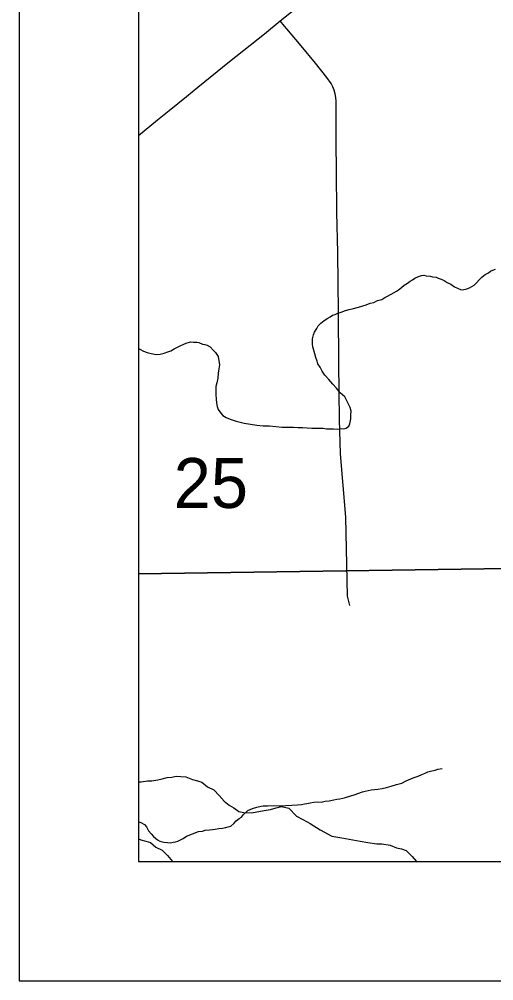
# Model space of a CAD drawing. Extents: x -21.1 to 50.3, y -4.9 to 22.1.
# Drawn here: x 2 to 2.398, y 14 to 14.806 of the extents above; entities that cross this region are included whole.
import ezdxf

# ---------------------------------------------------------------- set-up
doc = ezdxf.new("R2010")
doc.units = 0
for name, color, linetype in [('GM_X_Corporation', 7, 'Continuous'), ('GM_X_County', 7, 'Continuous'), ('GM_X_Minor_River', 7, 'Continuous'), ('GM_X_Rail_Line_Text', 7, 'Continuous'), ('GM_X_Section_Text', 7, 'Continuous'), ('GM_X_State_Route', 7, 'Continuous'), ('GM_X_Township_Road', 7, 'Continuous'), ('SH_Cut_Line', 7, 'Continuous'), ('SH_Data', 7, 'Continuous')]:
    doc.layers.add(name, color=color, linetype=linetype)

msp = doc.modelspace()

# ---------------------------------------------------------------- linework, layer by layer
at = {"layer": 'GM_X_Corporation'}
for points in [[(2.1, 15.34422), (2.1, 14.34116), (2.8725, 14.35222), (2.86184, 15.35457)], [(2.1, 14.34116), (2.1, 14.1), (2.87676, 14.1), (2.8725, 14.35222)]]:
    msp.add_lwpolyline(points, close=True, dxfattribs=at)
at = {"layer": 'GM_X_County'}
msp.add_lwpolyline([(8.9, 14.74638), (8.9, 20.9), (2.1, 20.9), (2.1, 14.1), (8.89319, 14.1)], dxfattribs=at)
at = {"layer": 'GM_X_Minor_River'}
for points in [[(2.26969, 14.56043), (2.27352, 14.56188), (2.27658, 14.56258), (2.28002, 14.56365), (2.28307, 14.56436), (2.28613, 14.56506), (2.28804, 14.56578), (2.29071, 14.56649), (2.29416, 14.56795), (2.29722, 14.56865), (2.30029, 14.57011), (2.30373, 14.57119), (2.30642, 14.57265), (2.30872, 14.57375), (2.3141, 14.57707), (2.31602, 14.57817), (2.31795, 14.57928), (2.32026, 14.58113), (2.32258, 14.58299), (2.32527, 14.58483), (2.32758, 14.58631), (2.3295, 14.58741), (2.33143, 14.5889), (2.3345, 14.59036), (2.33718, 14.59107), (2.33908, 14.59141), (2.34098, 14.591), (2.34439, 14.59056), (2.34628, 14.59014), (2.34932, 14.5897), (2.3512, 14.58891), (2.35347, 14.58811), (2.35611, 14.58692), (2.35874, 14.58535), (2.36175, 14.58378), (2.36476, 14.58182), (2.3674, 14.58063), (2.36965, 14.57945), (2.37155, 14.57904), (2.37499, 14.58011), (2.37728, 14.58083), (2.3792, 14.58193), (2.38113, 14.58304), (2.38306, 14.5849), (2.38539, 14.58751), (2.38771, 14.58975), (2.39042, 14.59198), (2.39311, 14.59344), (2.39504, 14.59493), (2.39695, 14.59565), (2.39924, 14.59637)], [(2.1, 14.52995), (2.10107, 14.52939), (2.10408, 14.52782), (2.1071, 14.52662), (2.11051, 14.5258), (2.11467, 14.52496), (2.1181, 14.52528), (2.12154, 14.52597), (2.1246, 14.52706), (2.1269, 14.52815), (2.12997, 14.52961), (2.13266, 14.53108), (2.13535, 14.53255), (2.13803, 14.53364), (2.13994, 14.53436), (2.14338, 14.53544), (2.14605, 14.53539), (2.1487, 14.53534), (2.1506, 14.53493), (2.15362, 14.53373), (2.15551, 14.53331), (2.15741, 14.5329), (2.16004, 14.53133), (2.16265, 14.52862), (2.16451, 14.52669), (2.16673, 14.52323), (2.16774, 14.51638), (2.1673, 14.51297), (2.16684, 14.50918), (2.16639, 14.50501), (2.16556, 14.50123), (2.16474, 14.49821), (2.16468, 14.49479), (2.16461, 14.49137), (2.16492, 14.48757), (2.16524, 14.48453), (2.16595, 14.48147), (2.16666, 14.4788), (2.16888, 14.47572), (2.17075, 14.47379), (2.17338, 14.47222), (2.17677, 14.47064), (2.18168, 14.46903), (2.18849, 14.46738), (2.1938, 14.46653), (2.19911, 14.46567), (2.20442, 14.46519), (2.20974, 14.46509), (2.21506, 14.46461), (2.22037, 14.46413), (2.22531, 14.46404), (2.22987, 14.46395), (2.23367, 14.46388), (2.23747, 14.46381), (2.24127, 14.46336), (2.24507, 14.46329), (2.24811, 14.46323), (2.25115, 14.46318), (2.25457, 14.46311), (2.2576, 14.46268), (2.26064, 14.46262), (2.2633, 14.46257), (2.26634, 14.46251), (2.26977, 14.46283), (2.27205, 14.46279), (2.27396, 14.46313), (2.27627, 14.46499), (2.27707, 14.46687), (2.27791, 14.47103), (2.27797, 14.47445), (2.27803, 14.47749), (2.27732, 14.48054), (2.27293, 14.48935), (2.26881, 14.49285), (2.26584, 14.4967), (2.26286, 14.50018), (2.25951, 14.50404), (2.25616, 14.50751), (2.25394, 14.51097), (2.2521, 14.51443), (2.25025, 14.51712), (2.24954, 14.51941), (2.24845, 14.52247), (2.24775, 14.52552), (2.24668, 14.52934), (2.24595, 14.53125), (2.24562, 14.53354), (2.24567, 14.53619), (2.2457, 14.53809), (2.24653, 14.54149), (2.24733, 14.54376), (2.24929, 14.54676), (2.25047, 14.54901), (2.25279, 14.55125), (2.25549, 14.55348), (2.25857, 14.55532), (2.26049, 14.55642), (2.26242, 14.5579), (2.26472, 14.55862), (2.26702, 14.55972), (2.26969, 14.56043)], [(2.13521, 14.11825), (2.13751, 14.11935), (2.14021, 14.12119), (2.15017, 14.12519), (2.1536, 14.1255), (2.15589, 14.12622), (2.15932, 14.12653), (2.16199, 14.12686), (2.16427, 14.1272), (2.16732, 14.12752), (2.17037, 14.12785), (2.17304, 14.12856), (2.17495, 14.1289), (2.17724, 14.12962), (2.17995, 14.13185), (2.18189, 14.13409), (2.1842, 14.13594), (2.18613, 14.13705), (2.18807, 14.13929), (2.19155, 14.14264), (2.19539, 14.14447), (2.19921, 14.14554), (2.20265, 14.14623), (2.20455, 14.14658), (2.20797, 14.14651), (2.2133, 14.14679), (2.21786, 14.14671), (2.22052, 14.14666), (2.22319, 14.14699), (2.22852, 14.14727), (2.23309, 14.14756), (2.23651, 14.14788), (2.23918, 14.14821), (2.24109, 14.14855), (2.24376, 14.14926), (2.24681, 14.14959), (2.24986, 14.14991), (2.2529, 14.14985), (2.25633, 14.15055), (2.25976, 14.15086), (2.26357, 14.15155), (2.26625, 14.15226), (2.26854, 14.1526), (2.2712, 14.15293), (2.2735, 14.15365), (2.28153, 14.15616), (2.28382, 14.15687), (2.28765, 14.15832), (2.28995, 14.15904), (2.29491, 14.16008), (2.30063, 14.16074), (2.30405, 14.16105), (2.30787, 14.16212), (2.3117, 14.16319), (2.31628, 14.16462), (2.32049, 14.16568), (2.32432, 14.16751), (2.33007, 14.17006), (2.33428, 14.1715), (2.33735, 14.17296), (2.34003, 14.17405), (2.34233, 14.17515), (2.34577, 14.17584), (2.34844, 14.17655), (2.35074, 14.17727), (2.35264, 14.17761), (2.35455, 14.17796)], [(2.1, 14.16667), (2.10206, 14.16686), (2.10735, 14.16764), (2.11113, 14.16766), (2.11605, 14.16845), (2.11983, 14.16923), (2.12398, 14.17039), (2.12776, 14.17079), (2.13154, 14.17157), (2.13533, 14.17121), (2.13949, 14.17086), (2.14518, 14.16861), (2.14935, 14.16749), (2.15315, 14.16637), (2.15771, 14.16259), (2.16303, 14.15996), (2.1676, 14.15542), (2.1718, 14.1505), (2.17599, 14.1471), (2.17979, 14.14484), (2.18397, 14.14182), (2.18814, 14.14108), (2.19458, 14.14074), (2.20515, 14.1427), (2.21045, 14.14348), (2.21536, 14.14503), (2.21989, 14.1462), (2.22595, 14.14471), (2.23243, 14.1379), (2.23775, 14.13527), (2.24383, 14.13188), (2.25219, 14.1266), (2.26207, 14.12133), (2.2704, 14.11986), (2.28556, 14.1169), (2.292, 14.11579), (2.29958, 14.11469), (2.30374, 14.11471), (2.31094, 14.11361), (2.31625, 14.11136), (2.32042, 14.11062), (2.32421, 14.10912), (2.32916, 14.1042), (2.33284, 14.1)], [(2.1, 14.13342), (2.10014, 14.13333), (2.10202, 14.13254), (2.10503, 14.13096), (2.10652, 14.12904), (2.10836, 14.12558), (2.11059, 14.12326), (2.11245, 14.12095), (2.11582, 14.11823), (2.1177, 14.11706), (2.12111, 14.11623), (2.12414, 14.11579), (2.1268, 14.11575), (2.12909, 14.11608), (2.131, 14.11643), (2.13291, 14.11715), (2.13521, 14.11825)], [(2.1, 14.11884), (2.10189, 14.11809), (2.10606, 14.11697), (2.10986, 14.11585), (2.11442, 14.11207), (2.11974, 14.10944), (2.12431, 14.1049), (2.1285, 14.1)]]:
    msp.add_lwpolyline(points, dxfattribs=at)
at = {"layer": 'GM_X_Rail_Line_Text'}
msp.add_lwpolyline([(2.1, 16.34915), (2.1, 14.1), (2.87846, 14.1)], dxfattribs=at)
at = {"layer": 'GM_X_State_Route'}
msp.add_lwpolyline([(2.1, 14.70856), (2.11595, 14.72162), (2.12555, 14.72946), (2.13278, 14.73533), (2.14004, 14.74117), (2.14974, 14.74895), (2.1763, 14.77046), (2.20539, 14.79378), (2.21865, 14.80455), (2.24881, 14.82903)], dxfattribs=at)
at = {"layer": 'GM_X_Township_Road'}
msp.add_lwpolyline([(2.27695, 14.31453), (2.27505, 14.32242), (2.27377, 14.38866), (2.26913, 14.44169), (2.26839, 14.47057), (2.26772, 14.51709), (2.26744, 14.56051), (2.26698, 14.61013), (2.26622, 14.64424), (2.26585, 14.67836), (2.2655, 14.70318), (2.2656, 14.71869), (2.2655, 14.72799), (2.26547, 14.7373), (2.26519, 14.74038), (2.26469, 14.74345), (2.26391, 14.74645), (2.2628, 14.74933), (2.26134, 14.75207), (2.25785, 14.75719), (2.24816, 14.7693), (2.23629, 14.78364), (2.2243, 14.79788), (2.2223, 14.80024), (2.21865, 14.80455)], dxfattribs=at)
at = {"layer": 'SH_Cut_Line'}
msp.add_lwpolyline([(3.8594, 16.36616), (2.98413, 16.34395), (2.8547, 16.35265), (2.35323, 16.35722), (2.1, 16.34915), (2.1, 14.1), (8.9, 14.1)], dxfattribs=at)
at = {"layer": 'SH_Data'}
for p, q in [((2, 21), (2, 14)), ((2.1, 14.1), (2.1, 14.1)), ((2, 14), (9, 14))]:
    msp.add_line(p, q, dxfattribs=at)

# ---------------------------------------------------------------- texts
at = {"layer": 'GM_X_Section_Text'}
msp.add_text('25', height=0.041856, rotation=0.00001, dxfattribs=at).set_placement((2.12944, 14.39631))

doc.saveas('drawing.dxf')
